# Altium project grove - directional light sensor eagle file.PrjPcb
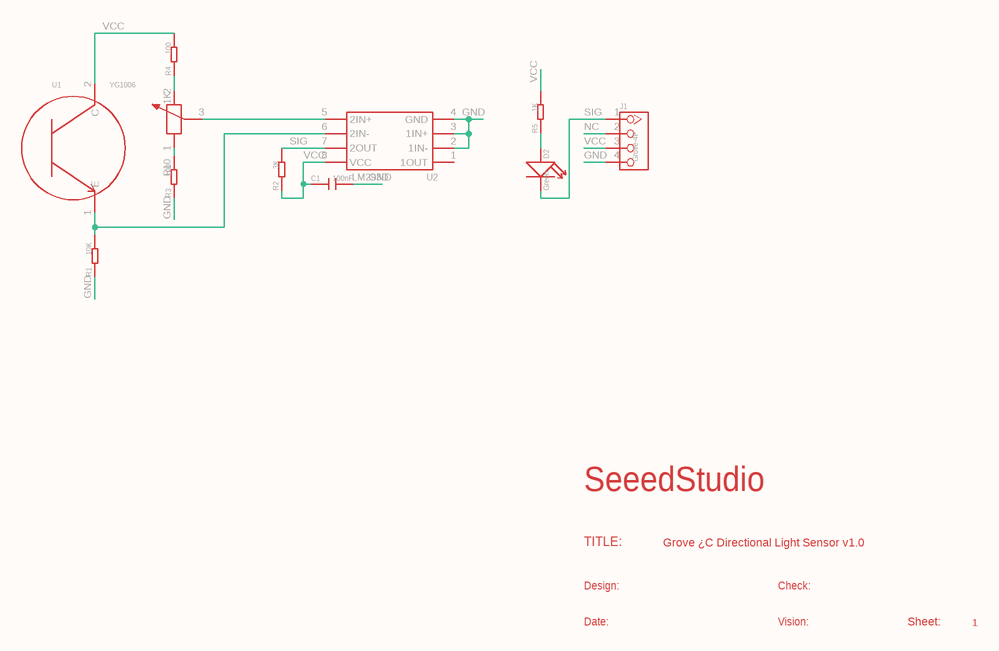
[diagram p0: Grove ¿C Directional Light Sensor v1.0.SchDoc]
1 sheet, 11 parts. Net scope: global (net labels, ports and power ports of the same name join across sheets).
Board file: Grove ¿C Directional Light Sensor v1.0.PcbDoc

## Sheet Grove ¿C Directional Light Sensor v1.0.SchDoc: Grove ¿C Directional Light Sensor v1.0
size 282 x 197 mm; SheetNumber: 1; Origin: Eagle; GateName_1: G$1; SymbolName_1: SEEEDSTUDIO_SCH_FRAME; LibraryName: moudle; DeviceSetName: SEEEDSTUDIO_SCH_FRAME; Sheet: Sheet:; SeeedStudio: SeeedStudio; Design: Design:; Check: Check:; Vision: Vision:

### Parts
C1  100nF  [C0603]
D2  Green  [LED-0603]
J1  Grove-4P  [4P-2.0]
R1  10K  [R0603]
R2  3K  [R0603]
R3  100  [R0603]
R4  100  [R0603]
R5  1K  [R0603]
R10  1K  [3P-SQUA-7X6.8]
U1  YG1006  [2P-2.54-5MM]
U2  LM293D  [SOIC8-6.0]

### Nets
GND: C1.2 J1.4 R1.1 R3.1 U2.2(1IN-) U2.3(1IN+) U2.4(GND)
NC: J1.2
SIG: D2.- J1.1 R2.2 U2.7(2OUT)
VCC: C1.1 J1.3 R2.1 R4.2 R5.2 U1.2(C) U2.8(VCC)
NetD2_+: D2.+ R5.1
NetR1_2: R1.2 U1.1(E) U2.6(2IN-)
NetR3_2: R3.2 R10.1
NetR4_1: R4.1 R10.2
NetR10_3: R10.3 U2.5(2IN+)

Not connected (* = marked no-connect by the designer): U2 1(1OUT)

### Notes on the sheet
- SeeedStudio
- TITLE:
- Design:
- Grove ¿C Directional Light Sensor v1.0
- Check:
- Date:
- Vision:
- Sheet:
- 1

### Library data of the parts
C1 = C*-0603: Ceramic Capacitors; GateName_1: C; DeviceName: -0603; DeviceSetName: C*
D2 = LED*'0603': GateName_1: LED; DeviceName: '0603'; DeviceSetName: LED*
J1 = TWIG-4P-2.0-2.0: GateName_1: G$1; SymbolName_1: TWIG_2.0; DeviceName: -2.0
R1-R5 = R*-0603: GateName_1: R; DeviceName: -0603; DeviceSetName: R*
R10 = R-POTENTIOMETER*'3362': Potentiometer; GateName_1: RP; SymbolName_1: POTEURO; DeviceName: '3362'
U1 = YG1006'YG1006': YG1006 is a high speed and high sensitive NPN siicon phototransistor in a atandard 5mm package; GateName_1: G$1
U2 = LM293D: Dual Differential Comparator; GateName_1: G$1; SymbolName_1: LM293; DeviceName: D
